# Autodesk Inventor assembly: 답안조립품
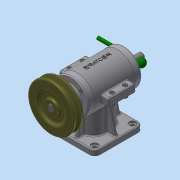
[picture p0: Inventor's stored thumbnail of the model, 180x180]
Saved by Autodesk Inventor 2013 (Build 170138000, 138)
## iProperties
Created: 2015-12
Part Number: 답안조립품
Document SubType Name: Assembly
Designer: Administrator
Author: Administrator
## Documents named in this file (19)
- C:\Users\Administrator\Desktop\351208V1032\답안조립품.iam
- C:\Users\Administrator\Desktop\351208V1032\본체.ipt
- C:\Users\Administrator\Desktop\351208V1032\V-벨트풀리.ipt
- C:\Users\Administrator\Desktop\351208V1032\너트 M4.ipt
- C:\Users\Administrator\Desktop\351208V1032\뒤커버.ipt
- C:\Users\Administrator\Desktop\351208V1032\레바.ipt
- C:\Users\Administrator\Desktop\351208V1032\멈춤나사 M3x8.ipt
- C:\Users\Administrator\Desktop\351208V1032\베어링 6201.ipt
- C:\Users\Administrator\Desktop\351208V1032\베어링 6202.ipt
- C:\Users\Administrator\Desktop\351208V1032\본체커버.ipt
- C:\Users\Administrator\Desktop\351208V1032\볼트 M3x0.5x8.ipt
- C:\Users\Administrator\Desktop\351208V1032\볼트 M4 x 16.ipt
- C:\Users\Administrator\Desktop\351208V1032\스프링.ipt
- C:\Users\Administrator\Desktop\351208V1032\슬라이드.ipt
- C:\Users\Administrator\Desktop\351208V1032\앞커버.ipt
- C:\Users\Administrator\Desktop\351208V1032\오일실 12 22 7.ipt
- C:\Users\Administrator\Desktop\351208V1032\와셔 ST 4-100.ipt
- C:\Users\Administrator\Desktop\351208V1032\키 4 x 4 x 18.ipt
- C:\Users\Administrator\Desktop\351208V1032\편심축.ipt
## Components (13 placed, 4 different names)
1. V-벨트풀리:1 — 플러쉬:1
2. ISO 4032 M4:1
3. ISO 4762 M4 x 16:1
4. ISO 7091 ST 4 - 100 HV:1
5. ISO 4762 M4 x 16:2
6. ISO 4762 M4 x 16:3
7. ISO 4762 M4 x 16:4
8. ISO 7091 ST 4 - 100 HV:2
9. ISO 7091 ST 4 - 100 HV:3
10. ISO 7091 ST 4 - 100 HV:4
11. ISO 4032 M4:2
12. ISO 4032 M4:3
13. ISO 4032 M4:4
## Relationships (1: Flush 1)
- 플러쉬:1 [Flush]: V-벨트풀리:1
